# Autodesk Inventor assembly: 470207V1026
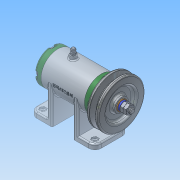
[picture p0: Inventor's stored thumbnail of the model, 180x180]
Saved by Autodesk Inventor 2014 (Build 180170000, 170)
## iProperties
Created: 2017-02
Part Number: 470207V1026
Document SubType Name: Assembly
Designer: NET
Author: NET
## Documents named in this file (16)
- C:\Users\NET\Desktop\470207V1026\답안조립품.iam
- C:\Users\NET\Desktop\470207V1026\본체.ipt
- C:\Users\NET\Desktop\470207V1026\V벨트풀리.ipt
- C:\Users\NET\Desktop\470207V1026\너트 M 8.ipt
- C:\Users\NET\Desktop\470207V1026\니플 M 6 x 0.75.ipt
- C:\Users\NET\Desktop\470207V1026\뒤커버.ipt
- C:\Users\NET\Desktop\470207V1026\베어링 15 x 32 x 9.ipt
- C:\Users\NET\Desktop\470207V1026\볼트 M 6 x 8.ipt
- C:\Users\NET\Desktop\470207V1026\볼트 M4 x 12.ipt
- C:\Users\NET\Desktop\470207V1026\스프링와셔 8.ipt
- C:\Users\NET\Desktop\470207V1026\앞커버.ipt
- C:\Users\NET\Desktop\470207V1026\오일 실 15 25 7.ipt
- C:\Users\NET\Desktop\470207V1026\와셔 6x11.5.ipt
- C:\Users\NET\Desktop\470207V1026\와셔 8x17.ipt
- C:\Users\NET\Desktop\470207V1026\축.ipt
- C:\Users\NET\Desktop\470207V1026\키 3 x 3 x 12.ipt
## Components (11 placed, 3 different names)
1. V벨트풀리:1
2. KS B 2023 6002 - 15 x 32 x 9:1
3. KS B 2023 6002 - 15 x 32 x 9:2
4. ISO 4762 M4 x 12:1
5. ISO 4762 M4 x 12:2
6. ISO 4762 M4 x 12:3
7. ISO 4762 M4 x 12:4
8. ISO 4762 M4 x 12:5
9. ISO 4762 M4 x 12:6
10. ISO 4762 M4 x 12:7
11. ISO 4762 M4 x 12:8
